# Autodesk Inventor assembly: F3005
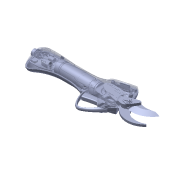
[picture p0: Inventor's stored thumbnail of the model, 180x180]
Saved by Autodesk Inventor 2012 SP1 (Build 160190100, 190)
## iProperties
Created: 2014-12
Part Number: F3005
Document SubType Name: Assembly
Designer: Bruno
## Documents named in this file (35)
- D:\Cours\Systèmes\secateur-hydrogene-Pragma\Documentation\Dossier technique Infaco F3005\Solidworks\Composants importés\F3005.iam
- D:\Cours\Systèmes\secateur-hydrogene-Pragma\Documentation\Dossier technique Infaco F3005\Solidworks\Composants importés\F3005\Tête sécateur.ipt
- D:\Cours\Systèmes\secateur-hydrogene-Pragma\Documentation\Dossier technique Infaco F3005\Solidworks\Composants importés\F3005\Crochet.ipt
- D:\Cours\Systèmes\secateur-hydrogene-Pragma\Documentation\Dossier technique Infaco F3005\Solidworks\Composants importés\F3005\Couronne.ipt
- D:\Cours\Systèmes\secateur-hydrogene-Pragma\Documentation\Dossier technique Infaco F3005\Solidworks\Composants importés\F3005\Pignon 9dts.ipt
- D:\Cours\Systèmes\secateur-hydrogene-Pragma\Documentation\Dossier technique Infaco F3005\Solidworks\Composants importés\F3005\Vis moteur.ipt
- D:\Cours\Systèmes\secateur-hydrogene-Pragma\Documentation\Dossier technique Infaco F3005\Solidworks\Composants importés\F3005\Vis lame M5x10.ipt
- D:\Cours\Systèmes\secateur-hydrogene-Pragma\Documentation\Dossier technique Infaco F3005\Solidworks\Composants importés\F3005\Coussinet lame_Cote mini.ipt
- D:\Cours\Systèmes\secateur-hydrogene-Pragma\Documentation\Dossier technique Infaco F3005\Solidworks\Composants importés\F3005\Gachette.ipt
- D:\Cours\Systèmes\secateur-hydrogene-Pragma\Documentation\Dossier technique Infaco F3005\Solidworks\Composants importés\F3005\Vis gachette.ipt
- D:\Cours\Systèmes\secateur-hydrogene-Pragma\Documentation\Dossier technique Infaco F3005\Solidworks\Composants importés\F3005\Axe lame_cote maxi.ipt
- D:\Cours\Systèmes\secateur-hydrogene-Pragma\Documentation\Dossier technique Infaco F3005\Solidworks\Composants importés\F3005\Lamelle blocage.ipt
- D:\Cours\Systèmes\secateur-hydrogene-Pragma\Documentation\Dossier technique Infaco F3005\Solidworks\Composants importés\F3005\Protection gachette.ipt
- D:\Cours\Systèmes\secateur-hydrogene-Pragma\Documentation\Dossier technique Infaco F3005\Solidworks\Composants importés\F3005\Bouton interrupteur.ipt
- D:\Cours\Systèmes\secateur-hydrogene-Pragma\Documentation\Dossier technique Infaco F3005\Solidworks\Composants importés\F3005\Ressort gachette.ipt
- D:\Cours\Systèmes\secateur-hydrogene-Pragma\Documentation\Dossier technique Infaco F3005\Solidworks\Composants importés\F3005\Vis tête.ipt
- D:\Cours\Systèmes\secateur-hydrogene-Pragma\Documentation\Dossier technique Infaco F3005\Solidworks\Composants importés\F3005\vis tête-2.ipt
- D:\Cours\Systèmes\secateur-hydrogene-Pragma\Documentation\Dossier technique Infaco F3005\Solidworks\Composants importés\F3005\Etiquette droite.ipt
- D:\Cours\Systèmes\secateur-hydrogene-Pragma\Documentation\Dossier technique Infaco F3005\Solidworks\Composants importés\F3005\Etiquette gauche.ipt
- D:\Cours\Systèmes\secateur-hydrogene-Pragma\Documentation\Dossier technique Infaco F3005\Solidworks\Composants importés\F3005\Vis carter 3x16.ipt
- D:\Cours\Systèmes\secateur-hydrogene-Pragma\Documentation\Dossier technique Infaco F3005\Solidworks\Composants importés\F3005\Vis carter 3x20.ipt
- D:\Cours\Systèmes\secateur-hydrogene-Pragma\Documentation\Dossier technique Infaco F3005\Solidworks\Composants importés\F3005\Vis carter 3x12.ipt
- D:\Cours\Systèmes\secateur-hydrogene-Pragma\Documentation\Dossier technique Infaco F3005\Solidworks\Composants importés\F3005\Vis M4X8.ipt
- D:\Cours\Systèmes\secateur-hydrogene-Pragma\Documentation\Dossier technique Infaco F3005\Solidworks\Composants importés\F3005\Rondelles M4.ipt
- D:\Cours\Systèmes\secateur-hydrogene-Pragma\Documentation\Dossier technique Infaco F3005\Solidworks\Composants importés\F3005\Crémaillère_Taillage.ipt
- D:\Cours\Systèmes\secateur-hydrogene-Pragma\Documentation\Dossier technique Infaco F3005\Solidworks\Composants importés\F3005\Lame_cote mini.ipt
- D:\Cours\Systèmes\secateur-hydrogene-Pragma\Documentation\Dossier technique Infaco F3005\Solidworks\Composants importés\F3005\LED complète.iam
- D:\Cours\Systèmes\secateur-hydrogene-Pragma\Documentation\Dossier technique Infaco F3005\Solidworks\Composants importés\F3005\Carte électrotique + connecteur.iam
- D:\Cours\Systèmes\secateur-hydrogene-Pragma\Documentation\Dossier technique Infaco F3005\Solidworks\Composants importés\F3005\Rondelle.ipt
- D:\Cours\Systèmes\secateur-hydrogene-Pragma\Documentation\Dossier technique Infaco F3005\Solidworks\Composants importés\F3005\Roulement tête.ipt
- D:\Cours\Systèmes\secateur-hydrogene-Pragma\Documentation\Dossier technique Infaco F3005\Solidworks\Composants importés\F3005\Motoréducteur.iam
- D:\Cours\Systèmes\secateur-hydrogene-Pragma\Documentation\Dossier technique Infaco F3005\Solidworks\Composants importés\F3005\Pignon 15dts.ipt
- D:\Cours\Systèmes\secateur-hydrogene-Pragma\Documentation\Dossier technique Infaco F3005\Solidworks\Composants importés\F3005\Vis pignon 15dts.ipt
- D:\Cours\Systèmes\secateur-hydrogene-Pragma\Documentation\Dossier technique Infaco F3005\Solidworks\Composants importés\F3005\Carter gauche.ipt
- D:\Cours\Systèmes\secateur-hydrogene-Pragma\Documentation\Dossier technique Infaco F3005\Solidworks\Composants importés\F3005\Carter droit.ipt
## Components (42 placed, 34 different names)
1. Tête sécateur:1
2. Crochet:1
3. Couronne:1
4. Pignon 9dts:1
5. Vis moteur:1
6. Vis moteur:2
7. Vis moteur:3
8. Vis moteur:4
9. Vis moteur:5
10. Vis lame M5x10:1
11. Coussinet lame_Cote mini:1
12. Gachette:1
13. Vis gachette:1
14. Axe lame_cote maxi:1
15. Lamelle blocage:1
16. Protection gachette:1
17. Bouton interrupteur:1
18. Ressort gachette:1
19. Vis tête:1
20. vis tête-2:1
21. Vis tête:2
22. Etiquette droite:1
23. Etiquette gauche:1
24. Vis carter 3x16:1
25. Vis carter 3x16:2
26. Vis carter 3x16:3
27. Vis carter 3x16:4
28. Vis carter 3x20:1
29. Vis carter 3x12:1
30. Vis M4X8:1
31. Rondelles M4:1
32. Crémaillère_Taillage:1
33. Lame_cote mini:1
34. LED complète:1 [sub-assembly]
35. Carte électrotique + connecteur:1 [sub-assembly]
36. Rondelle:1
37. Roulement tête:1
38. Motoréducteur:1 [sub-assembly]
39. Pignon 15dts:1
40. Vis pignon 15dts:1
41. Carter gauche:1
42. Carter droit:1
